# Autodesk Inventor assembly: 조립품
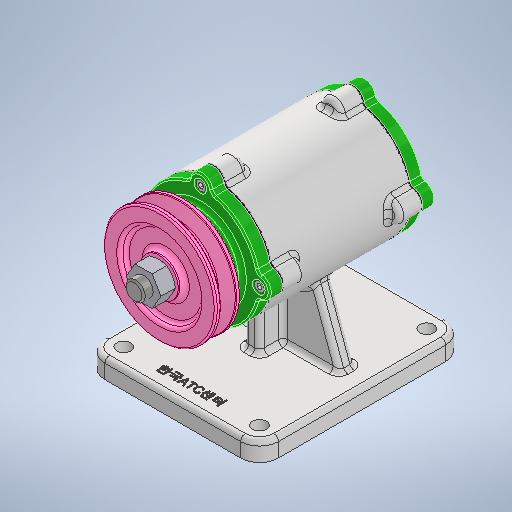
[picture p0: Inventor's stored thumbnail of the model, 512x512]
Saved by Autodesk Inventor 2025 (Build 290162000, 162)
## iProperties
Created: 2024-08
Part Number: 조립품
Document SubType Name: Assembly
Designer: onair
Author: onair
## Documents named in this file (12)
- C:\Users\onair\OneDrive\Desktop\740807V1007\조립품.iam
- C:\Users\onair\OneDrive\Desktop\740807V1007\본체.ipt
- C:\Users\onair\OneDrive\Desktop\740807V1007\V-벨트풀리\V-벨트풀리.ipt
- C:\Users\onair\OneDrive\Desktop\740807V1007\개스킷\개스킷.ipt
- C:\Users\onair\OneDrive\Desktop\740807V1007\너트 M12 x 1.25\너트 M12 x 1.25.ipt
- C:\Users\onair\OneDrive\Desktop\740807V1007\뒤커버\뒤커버.ipt
- C:\Users\onair\OneDrive\Desktop\740807V1007\베어링 6204\베어링 6204.ipt
- C:\Users\onair\OneDrive\Desktop\740807V1007\볼트 M4 x 12\볼트 M4 x 12.ipt
- C:\Users\onair\OneDrive\Desktop\740807V1007\앞커버\앞커버.ipt
- C:\Users\onair\OneDrive\Desktop\740807V1007\오일실\오일실.ipt
- C:\Users\onair\OneDrive\Desktop\740807V1007\축\축.ipt
- C:\Users\onair\OneDrive\Desktop\740807V1007\키 4 x 4\키 4 x 4.ipt
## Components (3 placed, 2 different names)
1. V-벨트풀리:1 — 각도:4
2. 개스킷:1
3. 개스킷:2
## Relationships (1: Angle 1)
- 각도:4 [Angle]: V-벨트풀리:1
